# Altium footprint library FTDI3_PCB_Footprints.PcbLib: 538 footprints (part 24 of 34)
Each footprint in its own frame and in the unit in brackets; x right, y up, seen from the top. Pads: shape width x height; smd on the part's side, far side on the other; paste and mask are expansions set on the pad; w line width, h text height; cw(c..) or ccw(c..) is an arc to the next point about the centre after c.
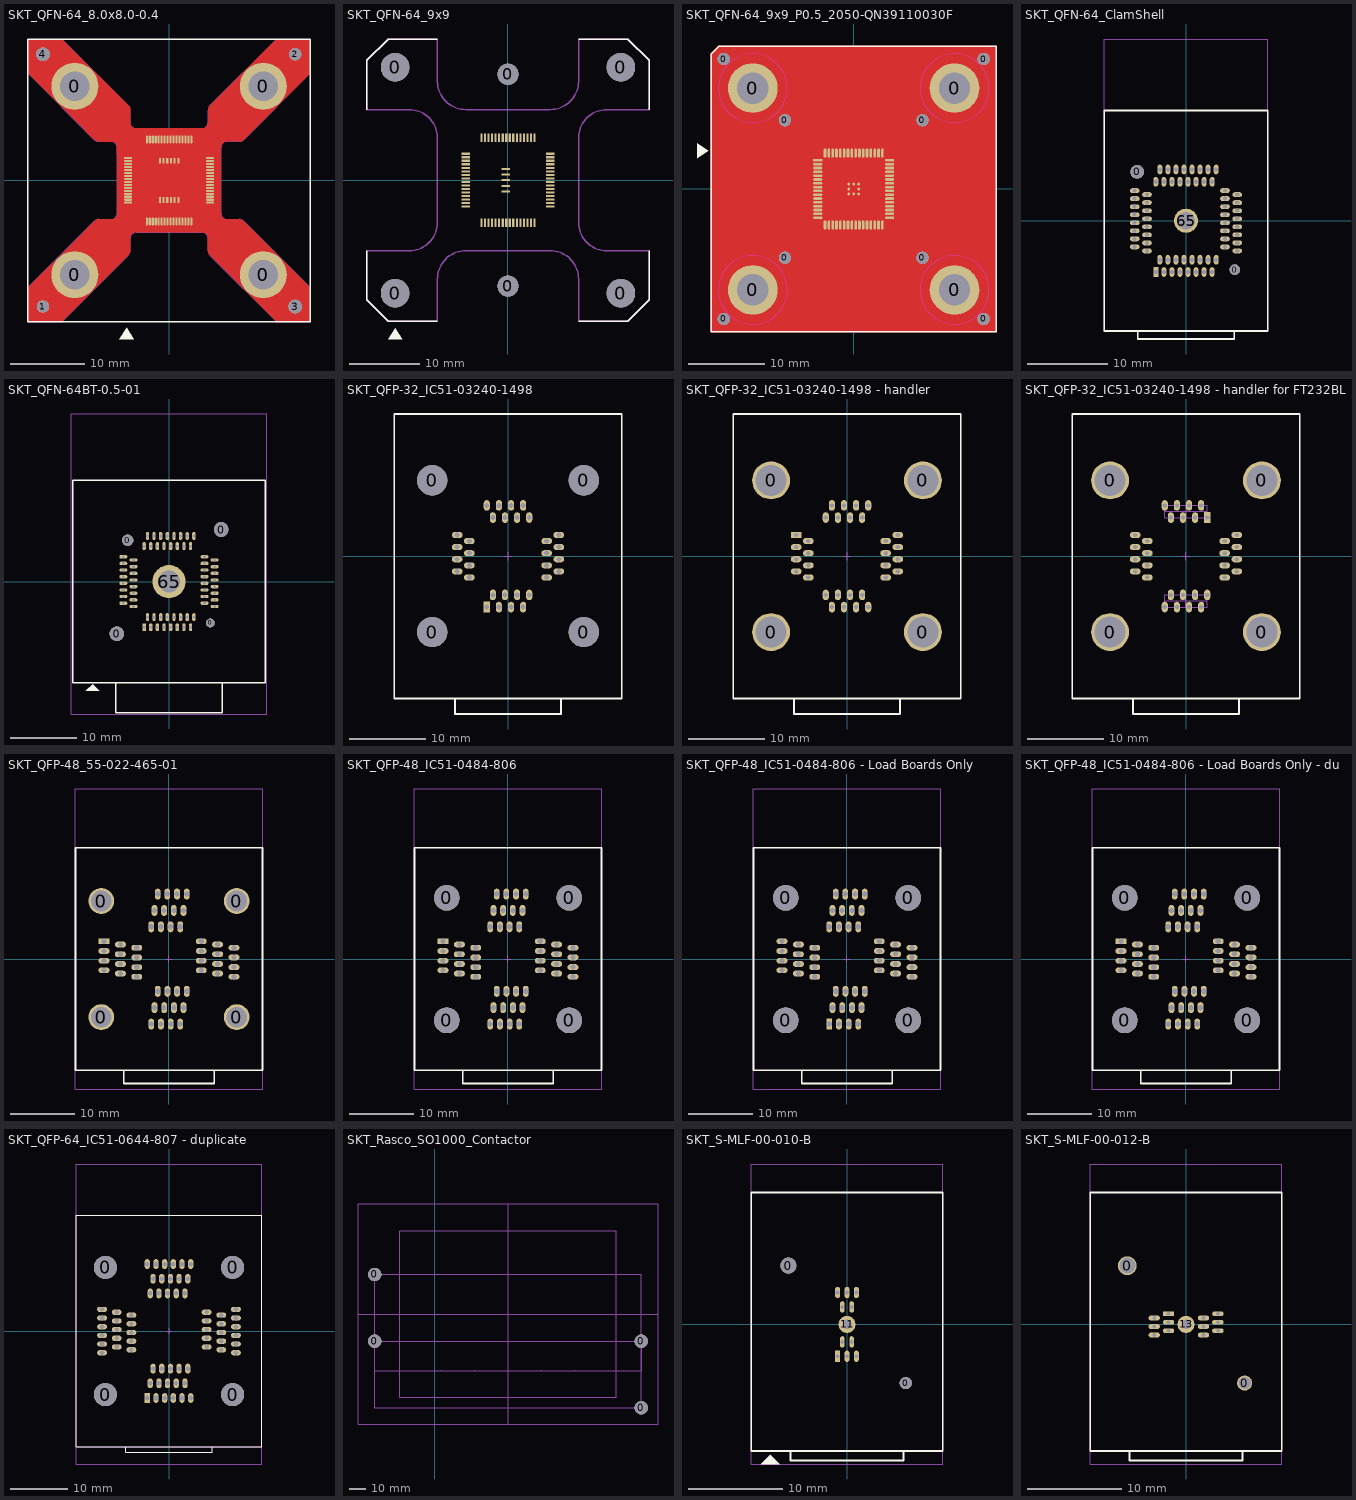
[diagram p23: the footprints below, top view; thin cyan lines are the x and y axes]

## SKT_QFN-64_8.0x8.0-0.4 [mm] "Load Board Socket for QFN-64; 8.0 x 8.0mm; 0.4mm pitch; Johnstech; Pad ROL(tm)200 series Production Test Contactor"
height 5.5
pads (84):
  round 6.35 hole 4: 0(-12.7,-12.7) 0(-12.7,12.7) 0(12.7,-12.7) 0(12.7,12.7)
  round 1.65 hole 1.65 unplated: 1(-17,-17) 2(17,17)
  oval 0.279x1.07 smd: 1(-3,-5.525) 2(-2.6,-5.525) 3(-2.2,-5.525) 4(-1.8,-5.525) 5(-1.4,-5.525) 6(-1,-5.525) 7(-0.6,-5.525) 8(-0.2,-5.525) 9(0.2,-5.525) 10(0.6,-5.525) 11(1,-5.525) 12(1.4,-5.525) 13(1.8,-5.525) 14(2.2,-5.525) 15(2.6,-5.525) 16(3,-5.525) 33(3,5.525) 34(2.6,5.525) 35(2.2,5.525) 36(1.8,5.525) 37(1.4,5.525) 38(1,5.525) 39(0.6,5.525) 40(0.2,5.525) 41(-0.2,5.525) 42(-0.6,5.525) 43(-1,5.525) 44(-1.4,5.525) 45(-1.8,5.525) 46(-2.2,5.525) 47(-2.6,5.525) 48(-3,5.525)
  round 1.85 hole 1.85 unplated: 3(17,-17) 4(-17,17)
  oval 1.07x0.279 smd: 17(5.525,-3) 18(5.525,-2.6) 19(5.525,-2.2) 20(5.525,-1.8) 21(5.525,-1.4) 22(5.525,-1) 23(5.525,-0.6) 24(5.525,-0.2) 25(5.525,0.2) 26(5.525,0.6) 27(5.525,1) 28(5.525,1.4) 29(5.525,1.8) 30(5.525,2.2) 31(5.525,2.6) 32(5.525,3) 49(-5.525,3) 50(-5.525,2.6) 51(-5.525,2.2) 52(-5.525,1.8) 53(-5.525,1.4) 54(-5.525,1) 55(-5.525,0.6) 56(-5.525,0.2) 57(-5.525,-0.2) 58(-5.525,-0.6) 59(-5.525,-1) 60(-5.525,-1.4) 61(-5.525,-1.8) 62(-5.525,-2.2) 63(-5.525,-2.6) 64(-5.525,-3)
  rect 0.28x0.8 smd: 65(-1.25,-2.65) 65(-1.25,2.65) 65(-0.75,-2.65) 65(-0.75,2.65) 65(-0.25,-2.65) 65(-0.25,2.65) 65(0.25,-2.65) 65(0.25,2.65) 65(0.75,-2.65) 65(0.75,2.65) 65(1.25,-2.65) 65(1.25,2.65)
Top Layer:
  pour cut-out: -19.05,19.06 -14.465,19.06 -14.465,19.05 -5.25,9.835 -5.25,7.52 -4.735,7.005 4.725,7.005 4.93,7.21 4.995,7.21 4.995,7.22 5.14,7.365 5.14,7.47 5.23,7.56 5.23,7.755 5.255,7.78 5.255,9.59 5.28,9.615 5.28,9.75 5.37,9.84 5.37,9.945 5.49,10.065 5.49,10.07 14.465,19.045 19.05,19.045 19.05,14.475 10.015,5.44 9.98,5.44 9.89,5.35 9.84,5.35 9.77,5.28 9.645,5.28 9.615,5.25 7.61,5.25 7.54,5.18 7.43,5.18 7.35,5.1 7.305,5.1 7.185,4.98 7.185,4.95 7.09,4.855 7.09,4.78 7.02,4.71 7.02,4.56 6.995,4.535 6.995,-4.515 7.015,-4.535 7.015,-4.675 7.055,-4.715 7.055,-4.795 7.14,-4.88 7.14,-4.92 7.37,-5.15 7.49,-5.15 7.565,-5.225 7.755,-5.225 7.785,-5.255 9.615,-5.255 9.64,-5.28 9.76,-5.28 9.82,-5.34 9.895,-5.34 10.04,-5.485 10.055,-5.485 19.045,-14.475 19.045,-19.055 18.81,-19.055 18.805,-19.06 14.48,-19.06 14.48,-19.05 5.34,-9.91 5.34,-9.83 5.3,-9.79 5.3,-9.735 5.275,-9.71 5.275,-9.64 5.25,-9.615 5.25,-9.525 5.245,-9.52 5.245,-7.72 5.23,-7.705 5.23,-7.585 5.19,-7.545 5.19,-7.465 5.135,-7.41 5.135,-7.385 5.06,-7.31 5.06,-7.285 4.975,-7.2 4.975,-7.195 4.96,-7.195 4.89,-7.125 4.86,-7.125 4.79,-7.055 4.705,-7.055 4.66,-7.01 4.54,-7.01 4.525,-6.995 -4.455,-6.995 -4.47,-7.01 -4.695,-7.01 -4.75,-7.065 -4.815,-7.065 -4.9,-7.15 -4.925,-7.15 -5.035,-7.26 -5.055,-7.26 -5.055,-7.285 -5.15,-7.38 -5.15,-7.425 -5.205,-7.48 -5.205,-7.59 -5.235,-7.62 -5.235,-7.805 -5.255,-7.825 -5.255,-9.69 -5.315,-9.75 -5.315,-9.845 -5.415,-9.945 -5.415,-9.985 -14.47,-19.04 -19.05,-19.04 -19.05,-14.455 -12.27,-7.7 -9.945,-5.39 -9.685,-5.265 -7.685,-5.245 -7.21,-5.03 -6.99,-4.495 -6.995,-2.835 -7,-0.085 -6.995,2.555 -7.02,4.655 -7.215,5 -7.595,5.23 -8.42,5.245 -9.27,5.23 -9.675,5.265 -9.985,5.41 -12.465,7.89 -19.07,14.485
Top Overlay:
  region: -5.73,-19.87 -4.73,-21.37 -6.73,-21.37
  lines w0.2: -19.05,-19.05 -19.05,19.05 19.05,19.05 19.05,-19.05 -19.05,-19.05
Top Solder:
  pour cut-out: -19.05,-19.05 -14.479,-19.05 -9.871,-14.443 -7.52,-12.08 -6.165,-10.736 -5.484,-10.056 -5.28,-9.8 -5.24,-9.55 -5.25,-9.3 -5.25,-7.8 -5.21,-7.49 -5.02,-7.24 -4.77,-7.04 -4.45,-7 4.45,-7 4.81,-7.05 5.05,-7.2 5.21,-7.48 5.25,-7.8 5.25,-9.49 5.3,-9.81 5.484,-10.056 14.479,-19.05 19.05,-19.05 19.05,-14.479 10.056,-5.484 9.8,-5.3 9.49,-5.25 7.8,-5.25 7.51,-5.19 7.26,-5.03 7.06,-4.77 7,-4.45 7,4.45 7.06,4.77 7.24,5.04 7.49,5.2 7.8,5.25 8.795,5.27 9.34,5.25 9.58,5.25 9.82,5.3 10.056,5.486 10.864,6.294 12.09,7.56 14.38,9.85 19.05,14.48 19.05,19.05 14.479,19.05 5.25,9.821 5.25,7.8 5.16,7.49 5.01,7.24 4.74,7.07 4.45,7 -4.45,7 -4.76,7.06 -5.04,7.23 -5.18,7.47 -5.25,7.8 -5.25,9.49 -5.32,9.81 -5.484,10.056 -14.479,19.05 -19.05,19.05 -19.05,14.479 -9.821,5.25 -7.8,5.25 -7.48,5.18 -7.22,4.99 -7.06,4.74 -7,4.45 -7,-4.45 -7.08,-4.78 -7.25,-5.04 -7.51,-5.18 -7.8,-5.25 -9.49,-5.25 -9.78,-5.3 -10.056,-5.484 -19.05,-14.479
M13_Assembly_Info:
  lines w0.1: -19.05,-19.05 -19.05,-14.479 -10.056,-5.484 cw(c-9.49,-6.05) -9.49,-5.25 -7.8,-5.25 ccw(c-7.8,-4.45) -7,-4.45 -7,4.45 ccw(c-7.8,4.45) -7.8,5.25 -9.49,5.25 cw(c-9.49,6.05) -10.056,5.484 -19.05,14.479 -19.05,19.05 -14.479,19.05 -5.484,10.056 cw(c-6.05,9.49) -5.25,9.49 -5.25,7.8 ccw(c-4.45,7.8) -4.45,7 4.45,7 ccw(c4.45,7.8) 5.25,7.8 5.25,9.49 cw(c6.05,9.49) 5.484,10.056 14.479,19.05 19.05,19.05 19.05,14.48 10.056,5.486 10.056,5.484 cw(c9.49,6.05) 9.49,5.25 7.8,5.25 ccw(c7.8,4.45) 7,4.45 7,-4.45 ccw(c7.8,-4.45) 7.8,-5.25 9.49,-5.25 cw(c9.49,-6.05) 10.056,-5.484 19.05,-14.479 19.05,-19.05 14.479,-19.05 5.484,-10.056 cw(c6.05,-9.49) 5.25,-9.49 5.25,-7.8 ccw(c4.45,-7.8) 4.45,-7 -4.45,-7 ccw(c-4.45,-7.8) -5.25,-7.8 -5.25,-9.49 cw(c-6.05,-9.49) -5.484,-10.056 -14.479,-19.05 -19.05,-19.05 ; -4,-4 4,-4 4,4 -4,4 -4,-4
M15_Country_Yard:
  lines w0.1: -0.5,0 0.5,0 ; 0,-0.5 0,0.5

## SKT_QFN-64_9x9 [mm]
pads (75):
  round 4.05 hole 4.05 unplated: 0(-16,-16) 0(-16,16) 0(16,-16) 0(16,16)
  round 3 hole 3 unplated: 0(0,-15) 0(0,15)
  rect 0.3x1.2 smd: 1(-3.75,-6) 2(-3.25,-6) 3(-2.75,-6) 4(-2.25,-6) 5(-1.75,-6) 6(-1.25,-6) 7(-0.75,-6) 8(-0.25,-6) 9(0.25,-6) 10(0.75,-6) 11(1.25,-6) 12(1.75,-6) 13(2.25,-6) 14(2.75,-6) 15(3.25,-6) 16(3.75,-6) 33(3.75,6) 34(3.25,6) 35(2.75,6) 36(2.25,6) 37(1.75,6) 38(1.25,6) 39(0.75,6) 40(0.25,6) 41(-0.25,6) 42(-0.75,6) 43(-1.25,6) 44(-1.75,6) 45(-2.25,6) 46(-2.75,6) 47(-3.25,6) 48(-3.75,6)
  rect 1.2x0.3 smd: 17(6,-3.75) 18(6,-3.25) 19(6,-2.75) 20(6,-2.25) 21(6,-1.75) 22(6,-1.25) 23(6,-0.75) 24(6,-0.25) 25(6,0.25) 26(6,0.75) 27(6,1.25) 28(6,1.75) 29(6,2.25) 30(6,2.75) 31(6,3.25) 32(6,3.75) 49(-6,3.75) 50(-6,3.25) 51(-6,2.75) 52(-6,2.25) 53(-6,1.75) 54(-6,1.25) 55(-6,0.75) 56(-6,0.25) 57(-6,-0.25) 58(-6,-0.75) 59(-6,-1.25) 60(-6,-1.75) 61(-6,-2.25) 62(-6,-2.75) 63(-6,-3.25) 64(-6,-3.75) 65(-0.3,-1.6) 65(-0.3,-0.8) 65(-0.3,0) 65(-0.3,0.8) 65(-0.3,1.6)
Top Overlay:
  region: -16,-21 -15,-22.5 -17,-22.5
  lines w0.2: -20,-10 -20,-16.975 -16.975,-20 -10,-20 ; -20,10 -20,16.975 -16.975,20 -10,20 ; 10,-20 16.975,-20 20,-16.975 20,-10 ; 10,20 16.975,20 20,16.975 20,10
M13_Assembly_Info:
  lines w0.2: 13.975,-10 20,-10 20,-16.975 16.975,-20 10,-20 10,-14 ccw(c6,-14) 6,-10 -6,-10 ccw(c-6,-14) -10,-14 -10,-20 -16.975,-20 -20,-16.975 -20,-10 -14,-10 ccw(c-14,-6) -10,-6 -10,6 ccw(c-14,6) -14,10 -20,10 -20,16.975 -16.975,20 -10,20 -10,14 ccw(c-6,14) -6,10 6,10 ccw(c6,14) 10,14 10,20 16.975,20 20,16.975 20,10 13.975,10 ; 14,-10 cw(c14,-6) 10,-6 10,6 cw(c14,6) 14,10

## SKT_QFN-64_9x9_P0.5_2050-QN39110030F [mm] "Tai-Chen Precision Inc. QFN-64 9x9mm body; 0.5mm pitch; Test Socket; 2050-QN39110030F"
height 6.6
pads (84):
  round 1.6 hole 1.6 unplated: 0(-17,-17) 0(-17,17) 0(-9,-9) 0(-9,9) 0(9,-9) 0(9,9) 0(17,-17) 0(17,17)
  round 6.5 hole 4.1: 0(-13.2,-13.2) 0(-13.2,13.2) 0(13.2,-13.2) 0(13.2,13.2)
  rect 1.2x0.35 smd: 1(-4.7,3.75)
  oval 1.2x0.35 smd: 2(-4.7,3.25) 3(-4.7,2.75) 4(-4.7,2.25) 5(-4.7,1.75) 6(-4.7,1.25) 7(-4.7,0.75) 8(-4.7,0.25) 9(-4.7,-0.25) 10(-4.7,-0.75) 11(-4.7,-1.25) 12(-4.7,-1.75) 13(-4.7,-2.25) 14(-4.7,-2.75) 15(-4.7,-3.25) 16(-4.7,-3.75) 33(4.7,-3.75) 34(4.7,-3.25) 35(4.7,-2.75) 36(4.7,-2.25) 37(4.7,-1.75) 38(4.7,-1.25) 39(4.7,-0.75) 40(4.7,-0.25) 41(4.7,0.25) 42(4.7,0.75) 43(4.7,1.25) 44(4.7,1.75) 45(4.7,2.25) 46(4.7,2.75) 47(4.7,3.25) 48(4.7,3.75)
  oval 0.35x1.2 smd: 17(-3.75,-4.7) 18(-3.25,-4.7) 19(-2.75,-4.7) 20(-2.25,-4.7) 21(-1.75,-4.7) 22(-1.25,-4.7) 23(-0.75,-4.7) 24(-0.25,-4.7) 25(0.25,-4.7) 26(0.75,-4.7) 27(1.25,-4.7) 28(1.75,-4.7) 29(2.25,-4.7) 30(2.75,-4.7) 31(3.25,-4.7) 32(3.75,-4.7) 49(3.75,4.7) 50(3.25,4.7) 51(2.75,4.7) 52(2.25,4.7) 53(1.75,4.7) 54(1.25,4.7) 55(0.75,4.7) 56(0.25,4.7) 57(-0.25,4.7) 58(-0.75,4.7) 59(-1.25,4.7) 60(-1.75,4.7) 61(-2.25,4.7) 62(-2.75,4.7) 63(-3.25,4.7) 64(-3.75,4.7)
  round 0.35 smd: 65(-0.66,-0.65) 65(-0.66,0) 65(-0.66,0.65) 65(-0.01,-0.65) 65(-0.01,0.65) 65(0.64,-0.65) 65(0.64,0) 65(0.64,0.65)
Top Layer:
  pour cut-out: -18.75,-18.75 -18.75,17.725 -17.725,18.75 18.75,18.75 18.75,-18.75
Top Overlay:
  region: -19,5 -20.5,4 -20.5,6
  lines w0.2: -18.65,-18.65 18.65,-18.65 18.65,18.65 -17.65,18.65 -18.65,17.65 -18.65,-18.65
Keep-Out Layer:
  circle w0.1: c-13.2,-13.2 r4.5
  circle w0.1: c13.2,-13.2 r4.5
  circle w0.1: c13.2,13.2 r4.5
  circle w0.1: c-13.2,13.2 r4.5
M15_Country_Yard:
  lines w0.1: -0.5,0 0.5,0 ; 0,-0.5 0,0.5

## SKT_QFN-64_ClamShell [mm] "Test & Burn socket for QFN-64"
height 15
pads (67):
  round 1.7 hole 1.7: 0(-6.075,6.075)
  round 1.3 hole 1.3: 0(6.075,-6.072)
  rect 0.6x1.2 hole 0.5: 1(-3.75,-6.375)
  oval 0.6x1.2 hole 0.5: 2(-3.25,-4.85) 3(-2.75,-6.375) 4(-2.25,-4.85) 5(-1.75,-6.375) 6(-1.25,-4.85) 7(-0.75,-6.375) 8(-0.25,-4.85) 9(0.25,-6.375) 10(0.75,-4.85) 11(1.25,-6.375) 12(1.75,-4.85) 13(2.25,-6.375) 14(2.75,-4.85) 15(3.25,-6.375) 16(3.75,-4.85) 33(3.75,6.376) 34(3.25,4.851) 35(2.75,6.376) 36(2.25,4.851) 37(1.75,6.376) 38(1.25,4.851) 39(0.75,6.376) 40(0.25,4.851) 41(-0.25,6.376) 42(-0.75,4.851) 43(-1.25,6.376) 44(-1.75,4.851) 45(-2.25,6.376) 46(-2.75,4.851) 47(-3.25,6.376) 48(-3.75,4.851)
  oval 1.2x0.6 hole 0.5: 17(6.373,-3.75) 18(4.848,-3.25) 19(6.373,-2.75) 20(4.848,-2.25) 21(6.373,-1.75) 22(4.848,-1.25) 23(6.373,-0.75) 24(4.848,-0.25) 25(6.373,0.25) 26(4.848,0.75) 27(6.373,1.25) 28(4.848,1.75) 29(6.373,2.25) 30(4.848,2.75) 31(6.373,3.25) 32(4.848,3.75) 49(-6.376,3.75) 50(-4.851,3.25) 51(-6.376,2.75) 52(-4.851,2.25) 53(-6.376,1.75) 54(-4.851,1.25) 55(-6.376,0.75) 56(-4.851,0.25) 57(-6.376,-0.25) 58(-4.851,-0.75) 59(-6.376,-1.25) 60(-4.851,-1.75) 61(-6.376,-2.25) 62(-4.851,-2.75) 63(-6.376,-3.25) 64(-4.851,-3.75)
  round 3 hole 2.2: 65(0,0)
Top Overlay:
  lines w0.2: -6,-13.715 -6,-14.707 6,-14.707 6,-13.715 ; -10.16,-13.715 -10.16,13.715 10.16,13.715 10.16,-13.715 -10.16,-13.715
M13_Assembly_Info:
  lines w0.1: -10.16,-13.715 -10.16,13.715 10.16,13.715 10.16,-13.715 -10.16,-13.715
M15_Country_Yard:
  lines w0.1: -10.16,13.715 -10.16,22.604 10.16,22.604 10.16,13.715

## SKT_QFN-64BT-0.5-01 [mm] "QFN-64BT-0.5-01 clamshell socket for QFN50P900X900X90-64"
height 16.7
pads (69):
  round 2.2 hole 2.2: 0(-7.85,-7.85) 0(7.85,7.85)
  round 1.7 hole 1.7: 0(-6.225,6.225)
  round 1.32 hole 1.32 unplated: 0(6.225,-6.225)
  rect 0.5x1.2 hole 0.4: 1(-3.75,-6.875)
  oval 0.5x1.2 hole 0.4: 2(-3.25,-5.35) 3(-2.75,-6.875) 4(-2.25,-5.35) 5(-1.75,-6.875) 6(-1.25,-5.35) 7(-0.75,-6.875) 8(-0.25,-5.35) 9(0.25,-6.875) 10(0.75,-5.35) 11(1.25,-6.875) 12(1.75,-5.35) 13(2.25,-6.875) 14(2.75,-5.35) 15(3.25,-6.875) 16(3.75,-5.35) 33(3.75,6.875) 34(3.25,5.35) 35(2.75,6.875) 36(2.25,5.35) 37(1.75,6.875) 38(1.25,5.35) 39(0.75,6.875) 40(0.25,5.35) 41(-0.25,6.875) 42(-0.75,5.35) 43(-1.25,6.875) 44(-1.75,5.35) 45(-2.25,6.875) 46(-2.75,5.35) 47(-3.25,6.875) 48(-3.75,5.35)
  oval 1.2x0.5 hole 0.4: 17(6.875,-3.75) 18(5.35,-3.25) 19(6.875,-2.75) 20(5.35,-2.25) 21(6.875,-1.75) 22(5.35,-1.25) 23(6.875,-0.75) 24(5.35,-0.25) 25(6.875,0.25) 26(5.35,0.75) 27(6.875,1.25) 28(5.35,1.75) 29(6.875,2.25) 30(5.35,2.75) 31(6.875,3.25) 32(5.35,3.75) 49(-6.875,3.75) 50(-5.35,3.25) 51(-6.875,2.75) 52(-5.35,2.25) 53(-6.875,1.75) 54(-5.35,1.25) 55(-6.875,0.75) 56(-5.35,0.25) 57(-6.875,-0.25) 58(-5.35,-0.75) 59(-6.875,-1.25) 60(-5.35,-1.75) 61(-6.875,-2.25) 62(-5.35,-2.75) 63(-6.875,-3.25) 64(-5.35,-3.75)
  round 5 hole 3.3: 65(0,0)
Top Overlay:
  region: -11.51,-15.45 -12.51,-16.45 -10.51,-16.45
  lines w0.2: -8,-15.25 -8,-19.75 8,-19.75 8,-15.25 ; -14.5,-15.25 14.5,-15.25 14.5,15.25 -14.5,15.25 -14.5,-15.25
M15_Country_Yard:
  lines w0.1: -14.69,-19.94 -14.69,25.25 14.69,25.25 14.69,-19.94 -14.69,-19.94

## SKT_QFP-32_IC51-03240-1498 [mm] "Test & Burn socket for QFP-32, 0.8mm pitch, 7x7mm body. Yamaichi IC51-03240-1498"
height 18.6
pads (36):
  round 4 hole 4 unplated: 0(-10,-10) 0(-10,10) 0(10,-10) 0(10,10)
  rect 0.8x1.4 hole 0.65: 1(-2.8,-6.7)
  oval 0.8x1.4 hole 0.65: 2(-2,-5.1) 3(-1.2,-6.7) 4(-0.4,-5.1) 5(0.4,-6.7) 6(1.2,-5.1) 7(2,-6.7) 8(2.8,-5.1) 17(2.8,5.1) 18(2,6.7) 19(1.2,5.1) 20(0.4,6.7) 21(-0.4,5.1) 22(-1.2,6.7) 23(-2,5.1) 24(-2.8,6.7)
  oval 1.4x0.8 hole 0.65: 9(5.1,-2.8) 10(6.7,-2) 11(5.1,-1.2) 12(6.7,-0.4) 13(5.1,0.4) 14(6.7,1.2) 15(5.1,2) 16(6.7,2.8) 25(-6.7,2.8) 26(-5.1,2) 27(-6.7,1.2) 28(-5.1,0.4) 29(-6.7,-0.4) 30(-5.1,-1.2) 31(-6.7,-2) 32(-5.1,-2.8)
Top Overlay:
  lines w0.25: -7,-20.8 -7,-18.75 7,-18.75 7,-20.8 -7,-20.8
  lines w0.254: -15,-18.75 -15,18.75 15,18.75 15,-18.75 -15,-18.75
M15_Country_Yard:
  lines w0.1: -0.5,0 0.5,0 ; 0,-0.5 0,0.5

## SKT_QFP-32_IC51-03240-1498 - handler [mm] "Test & Burn socket for QFP-32, 0.8mm pitch, 7x7mm body. Yamaichi IC51-03240-1498"
height 18.6
pads (36):
  round 5 hole 4.1: 0(-10,-10) 0(-10,10) 0(10,-10) 0(10,10)
  rect 1.4x0.8 hole 0.55: 1(-6.7,2.8)
  oval 1.4x0.8 hole 0.55: 2(-5.1,2) 3(-6.7,1.2) 4(-5.1,0.4) 5(-6.7,-0.4) 6(-5.1,-1.2) 7(-6.7,-2) 8(-5.1,-2.8) 17(5.1,-2.8) 18(6.7,-2) 19(5.1,-1.2) 20(6.7,-0.4) 21(5.1,0.4) 22(6.7,1.2) 23(5.1,2) 24(6.7,2.8)
  oval 0.8x1.4 hole 0.55: 9(-2.8,-5.1) 10(-2,-6.7) 11(-1.2,-5.1) 12(-0.4,-6.7) 13(0.4,-5.1) 14(1.2,-6.7) 15(2,-5.1) 16(2.8,-6.7) 25(2.8,6.7) 26(2,5.1) 27(1.2,6.7) 28(0.4,5.1) 29(-0.4,6.7) 30(-1.2,5.1) 31(-2,6.7) 32(-2.8,5.1)
Top Overlay:
  lines w0.25: -7,-20.8 -7,-18.75 7,-18.75 7,-20.8 -7,-20.8
  lines w0.254: -15,-18.75 -15,18.75 15,18.75 15,-18.75 -15,-18.75
M15_Country_Yard:
  lines w0.1: -0.5,0 0.5,0 ; 0,-0.5 0,0.5

## SKT_QFP-32_IC51-03240-1498 - handler for FT232BL [mm] "Test & Burn socket for QFP-32, 0.8mm pitch, 7x7mm body. Yamaichi IC51-03240-1498"
height 18.6
pads (36):
  round 5 hole 4.1: 0(-10,-10) 0(-10,10) 0(10,-10) 0(10,10)
  rect 0.8x1.4 hole 0.55: 1(2.8,5.1)
  oval 0.8x1.4 hole 0.55: 2(2,6.7) 3(1.2,5.1) 4(0.4,6.7) 5(-0.4,5.1) 6(-1.2,6.7) 7(-2,5.1) 8(-2.8,6.7) 17(-2.8,-6.7) 18(-2,-5.1) 19(-1.2,-6.7) 20(-0.4,-5.1) 21(0.4,-6.7) 22(1.2,-5.1) 23(2,-6.7) 24(2.8,-5.1)
  oval 1.4x0.8 hole 0.55: 9(-6.7,2.8) 10(-5.1,2) 11(-6.7,1.2) 12(-5.1,0.4) 13(-6.7,-0.4) 14(-5.1,-1.2) 15(-6.7,-2) 16(-5.1,-2.8) 25(5.1,-2.8) 26(6.7,-2) 27(5.1,-1.2) 28(6.7,-0.4) 29(5.1,0.4) 30(6.7,1.2) 31(5.1,2) 32(6.7,2.8)
Top Overlay:
  lines w0.25: -7,-20.8 7,-20.8 7,-18.75 -7,-18.75 -7,-20.8
  lines w0.254: -15,-18.75 15,-18.75 15,18.75 -15,18.75 -15,-18.75
M15_Country_Yard:
  lines w0.1: -2.8,-5.9 2.8,-5.9 ; -2.8,5.9 2.8,5.9 ; -0.5,0 0.5,0 ; 0,-6.7 0,-5.1 ; 0,-0.5 0,0.5 ; 0,5.1 0,6.7 ; -2.8,-6.7 2.8,-6.7 2.8,-5.1 -2.8,-5.1 -2.8,-6.7 ; -2.8,5.1 -2.8,6.7 2.8,6.7 2.8,5.1 -2.8,5.1

## SKT_QFP-48_55-022-465-01 [mm] "Test & Burn socket for QFP-48, 0.5mm pitch, 7x7mm body. Enplas, 55-022-465-01"
height 18.6
pads (52):
  round 4 hole 3.2 unplated: 0(-10.5,-9) 0(-10.5,9) 0(10.5,-9) 0(10.5,9)
  rect 1.7x0.9 hole 0.8: 1(-10.08,2.75)
  oval 1.7x0.9 hole 0.8: 2(-7.54,2.25) 3(-5,1.75) 4(-10.08,1.25) 5(-7.54,0.75) 6(-5,0.25) 7(-10.08,-0.26) 8(-7.54,-0.76) 9(-5,-1.26) 10(-10.08,-1.75) 11(-7.54,-2.25) 12(-5,-2.75) 25(10.08,-2.75) 26(7.54,-2.25) 27(5,-1.75) 28(10.08,-1.25) 29(7.54,-0.75) 30(5,-0.25) 31(10.08,0.26) 32(7.54,0.76) 33(5,1.26) 34(10.08,1.75) 35(7.54,2.25) 36(5,2.75)
  oval 0.9x1.7 hole 0.8: 13(-2.75,-10.08) 14(-2.25,-7.54) 15(-1.75,-5) 16(-1.25,-10.08) 17(-0.75,-7.54) 18(-0.25,-5) 19(0.26,-10.08) 20(0.76,-7.54) 21(1.26,-5) 22(1.75,-10.08) 23(2.25,-7.54) 24(2.75,-5) 37(2.75,10.08) 38(2.25,7.54) 39(1.75,5) 40(1.25,10.08) 41(0.75,7.54) 42(0.25,5) 43(-0.26,10.08) 44(-0.76,7.54) 45(-1.26,5) 46(-1.75,10.08) 47(-2.25,7.54) 48(-2.75,5)
Top Overlay:
  lines w0.25: -7,-17.25 -7,-19.3 7,-19.3 7,-17.25 ; -14.5,-17.25 -14.5,17.25 14.5,17.25 14.5,-17.25 -14.5,-17.25
M15_Country_Yard:
  lines w0.1: -0.5,0 0.5,0 ; 0,-0.5 0,0.5 ; -14.5,-20.15 14.5,-20.15 14.5,26.37 -14.5,26.37 -14.5,-20.15
3D body: height 15, standoff 0, extent -14.5,-17.25 14.5,17.25

## SKT_QFP-48_IC51-0484-806 [mm] "Test & Burn socket for QFP-48, 0.5mm pitch, 7x7mm body. Yamaichi, IC51-0484-806"
height 18.6
pads (52):
  round 4 hole 4 unplated: 0(-9.5,-9.5) 0(-9.5,9.5) 0(9.5,-9.5) 0(9.5,9.5)
  rect 1.7x0.9 hole 0.8: 1(-10.08,2.75)
  oval 1.7x0.9 hole 0.8: 2(-7.54,2.25) 3(-5,1.75) 4(-10.08,1.25) 5(-7.54,0.75) 6(-5,0.25) 7(-10.08,-0.26) 8(-7.54,-0.76) 9(-5,-1.26) 10(-10.08,-1.75) 11(-7.54,-2.25) 12(-5,-2.75) 25(10.08,-2.75) 26(7.54,-2.25) 27(5,-1.75) 28(10.08,-1.25) 29(7.54,-0.75) 30(5,-0.25) 31(10.08,0.26) 32(7.54,0.76) 33(5,1.26) 34(10.08,1.75) 35(7.54,2.25) 36(5,2.75)
  oval 0.9x1.7 hole 0.8: 13(-2.75,-10.08) 14(-2.25,-7.54) 15(-1.75,-5) 16(-1.25,-10.08) 17(-0.75,-7.54) 18(-0.25,-5) 19(0.26,-10.08) 20(0.76,-7.54) 21(1.26,-5) 22(1.75,-10.08) 23(2.25,-7.54) 24(2.75,-5) 37(2.75,10.08) 38(2.25,7.54) 39(1.75,5) 40(1.25,10.08) 41(0.75,7.54) 42(0.25,5) 43(-0.26,10.08) 44(-0.76,7.54) 45(-1.26,5) 46(-1.75,10.08) 47(-2.25,7.54) 48(-2.75,5)
Top Overlay:
  lines w0.25: -7,-17.25 -7,-19.3 7,-19.3 7,-17.25 ; -14.5,-17.25 14.5,-17.25 14.5,17.25 -14.5,17.25 -14.5,-17.25
M15_Country_Yard:
  lines w0.1: -0.5,0 0.5,0 ; 0,-0.5 0,0.5 ; -14.5,-20.15 -14.5,26.37 14.5,26.37 14.5,-20.15 -14.5,-20.15
3D body: height 15, standoff 0, extent -14.5,-17.25 14.5,17.25

## SKT_QFP-48_IC51-0484-806 - Load Boards Only [mm] "Test & Burn socket for QFP-48, 0.5mm pitch, 7x7mm body. Yamaichi, IC51-0484-806; Use only for Load Boards; Pin No. 1 rotated by 90 degrees"
height 18.6
pads (52):
  round 4 hole 4 unplated: 0(-9.5,-9.5) 0(-9.5,9.5) 0(9.5,-9.5) 0(9.5,9.5)
  rect 0.9x1.7 hole 0.8: 1(-2.75,-10.08)
  oval 0.9x1.7 hole 0.8: 2(-2.25,-7.54) 3(-1.75,-5) 4(-1.25,-10.08) 5(-0.75,-7.54) 6(-0.25,-5) 7(0.26,-10.08) 8(0.76,-7.54) 9(1.26,-5) 10(1.75,-10.08) 11(2.25,-7.54) 12(2.75,-5) 25(2.75,10.08) 26(2.25,7.54) 27(1.75,5) 28(1.25,10.08) 29(0.75,7.54) 30(0.25,5) 31(-0.26,10.08) 32(-0.76,7.54) 33(-1.26,5) 34(-1.75,10.08) 35(-2.25,7.54) 36(-2.75,5)
  oval 1.7x0.9 hole 0.8: 13(10.08,-2.75) 14(7.54,-2.25) 15(5,-1.75) 16(10.08,-1.25) 17(7.54,-0.75) 18(5,-0.25) 19(10.08,0.26) 20(7.54,0.76) 21(5,1.26) 22(10.08,1.75) 23(7.54,2.25) 24(5,2.75) 37(-10.08,2.75) 38(-7.54,2.25) 39(-5,1.75) 40(-10.08,1.25) 41(-7.54,0.75) 42(-5,0.25) 43(-10.08,-0.26) 44(-7.54,-0.76) 45(-5,-1.26) 46(-10.08,-1.75) 47(-7.54,-2.25) 48(-5,-2.75)
Top Overlay:
  lines w0.25: -7,-17.25 -7,-19.3 7,-19.3 7,-17.25 ; -14.5,-17.25 14.5,-17.25 14.5,17.25 -14.5,17.25 -14.5,-17.25
M15_Country_Yard:
  lines w0.1: -0.5,0 0.5,0 ; 0,-0.5 0,0.5 ; -14.5,-20.15 -14.5,26.37 14.5,26.37 14.5,-20.15 -14.5,-20.15
3D body: height 15, standoff 0, extent -14.5,-17.25 14.5,17.25

## SKT_QFP-48_IC51-0484-806 - Load Boards Only - duplicate1 [mm] "Test & Burn socket for QFP-48, 0.5mm pitch, 7x7mm body. Yamaichi, IC51-0484-806; Use only for Load Boards; Pin No. 1 rotated by 180 degrees"
height 18.6
pads (52):
  round 4 hole 4 unplated: 0(-9.5,-9.5) 0(-9.5,9.5) 0(9.5,-9.5) 0(9.5,9.5)
  rect 1.7x0.9 hole 0.8: 1(-10.08,2.75)
  oval 1.7x0.9 hole 0.8: 2(-7.54,2.25) 3(-5,1.75) 4(-10.08,1.25) 5(-7.54,0.75) 6(-5,0.25) 7(-10.08,-0.26) 8(-7.54,-0.76) 9(-5,-1.26) 10(-10.08,-1.75) 11(-7.54,-2.25) 12(-5,-2.75) 25(10.08,-2.75) 26(7.54,-2.25) 27(5,-1.75) 28(10.08,-1.25) 29(7.54,-0.75) 30(5,-0.25) 31(10.08,0.26) 32(7.54,0.76) 33(5,1.26) 34(10.08,1.75) 35(7.54,2.25) 36(5,2.75)
  oval 0.9x1.7 hole 0.8: 13(-2.75,-10.08) 14(-2.25,-7.54) 15(-1.75,-5) 16(-1.25,-10.08) 17(-0.75,-7.54) 18(-0.25,-5) 19(0.26,-10.08) 20(0.76,-7.54) 21(1.26,-5) 22(1.75,-10.08) 23(2.25,-7.54) 24(2.75,-5) 37(2.75,10.08) 38(2.25,7.54) 39(1.75,5) 40(1.25,10.08) 41(0.75,7.54) 42(0.25,5) 43(-0.26,10.08) 44(-0.76,7.54) 45(-1.26,5) 46(-1.75,10.08) 47(-2.25,7.54) 48(-2.75,5)
Top Overlay:
  lines w0.25: -7,-17.25 -7,-19.3 7,-19.3 7,-17.25 ; -14.5,-17.25 14.5,-17.25 14.5,17.25 -14.5,17.25 -14.5,-17.25
M15_Country_Yard:
  lines w0.1: -0.5,0 0.5,0 ; 0,-0.5 0,0.5 ; -14.5,-20.15 -14.5,26.37 14.5,26.37 14.5,-20.15 -14.5,-20.15
3D body: height 15, standoff 0, extent -14.5,-17.25 14.5,17.25

## SKT_QFP-64_IC51-0644-807 - duplicate [mm] "Test & Burn socket for QFP-64, 0.5mm pitch, 10x10mm body. Yamaichi, IC51-0644-807"
height 15
pads (68):
  round 4 hole 4 unplated: 0(-10.999,-10.997) 0(-10.999,10.999) 0(10.998,-10.997) 0(10.998,10.999)
  rect 0.9x1.7 hole 0.8: 1(-3.751,-11.582)
  oval 0.9x1.7 hole 0.8: 2(-3.251,-9.042) 3(-2.751,-6.502) 4(-2.251,-11.582) 5(-1.751,-9.042) 6(-1.251,-6.502) 7(-0.751,-11.582) 8(-0.251,-9.042) 9(0.249,-6.502) 10(0.749,-11.582) 11(1.249,-9.042) 12(1.749,-6.502) 13(2.249,-11.582) 14(2.749,-9.042) 15(3.249,-6.502) 16(3.749,-11.582) 33(3.749,11.582) 34(3.249,9.042) 35(2.749,6.502) 36(2.249,11.582) 37(1.749,9.042) 38(1.249,6.502) 39(0.749,11.582) 40(0.249,9.042) 41(-0.251,6.502) 42(-0.751,11.582) 43(-1.251,9.042) 44(-1.751,6.502) 45(-2.251,11.582) 46(-2.751,9.042) 47(-3.251,6.502) 48(-3.751,11.582)
  oval 1.7x0.9 hole 0.8: 17(11.582,-3.751) 18(9.042,-3.251) 19(6.502,-2.751) 20(11.582,-2.251) 21(9.042,-1.751) 22(6.502,-1.251) 23(11.582,-0.751) 24(9.042,-0.251) 25(6.502,0.249) 26(11.582,0.749) 27(9.042,1.249) 28(6.502,1.749) 29(11.582,2.249) 30(9.042,2.749) 31(6.502,3.249) 32(11.582,3.749) 49(-11.583,3.749) 50(-9.043,3.249) 51(-6.503,2.749) 52(-11.583,2.249) 53(-9.043,1.749) 54(-6.503,1.249) 55(-11.583,0.749) 56(-9.043,0.249) 57(-6.503,-0.251) 58(-11.583,-0.751) 59(-9.043,-1.251) 60(-6.503,-1.751) 61(-11.583,-2.251) 62(-9.043,-2.751) 63(-6.503,-3.251) 64(-11.583,-3.751)
Top Overlay:
  lines w0.2: -7.501,-19.999 -7.501,-20.93 7.499,-20.93 7.499,-19.999 ; -16,-19.999 16,-19.999 16,20.001 -16,20.001 -16,-19.999
M13_Assembly_Info:
  lines w0.1: -16,-19.999 16,-19.999 16,20.001 -16,20.001 -16,-19.999
M15_Country_Yard:
  lines w0.1: -16,-20 -16,-23 16,-23 16,-20 ; -16,20.001 -16,28.891 16,28.891 16,20.001 ; -0.5,0 0.5,0 ; 0,-0.5 0,0.5

## SKT_Rasco_SO1000_Contactor [mm]
pads (4):
  round 8 hole 8 unplated: 0(-35.93,134.21) 0(-35.93,174.21) 0(124.07,94.21) 0(124.07,134.21)
M15_Country_Yard:
  lines w0.1: -45.93,150.51 134.07,150.51 ; -35.93,116.43 124.07,116.43 ; -35.93,134.21 124.07,134.21 ; -20.93,150.51 109.07,150.51 ; 3.91,116.1 3.91,116.74 ; 24.23,116.1 24.23,116.74 ; 44.07,84.26 44.07,216.76 ; 44.07,94.21 44.07,174.21 ; 44.07,100.51 44.07,200.51 ; 63.91,116.1 63.91,116.74 ; 84.23,116.1 84.23,116.74 ; 124.3,116.43 124.3,134.21 ; -45.93,84.26 -45.93,216.76 134.07,216.76 134.07,84.26 -45.93,84.26 ; -35.93,94.21 -35.93,174.21 124.07,174.21 124.07,94.21 -35.93,94.21 ; -20.93,100.51 -20.93,200.51 109.07,200.51 109.07,100.51 -20.93,100.51

## SKT_S-MLF-00-010-B [mm] "Test & Burn socket for QFN-10, 0.5mm pitch, 3x3mm body. Emulation Technology S-MLF-00-010-B"
height 15
pads (13):
  round 1.7 hole 1.7 unplated: 0(-6.225,6.225)
  round 1.3 hole 1.3 unplated: 0(6.225,-6.225)
  rect 0.5x1.2 hole 0.4: 1(-1,-3.38)
  oval 0.5x1.2 hole 0.4: 2(-0.5,-1.855) 3(0,-3.38) 4(0.5,-1.855) 5(1,-3.38) 6(1,3.38) 7(0.5,1.855) 8(0,3.38) 9(-0.5,1.855) 10(-1,3.38)
  round 1.8 hole 1: 11(0,0)
Top Overlay:
  region: -8.14,-13.805 -7.14,-14.805 -9.14,-14.805
  lines w0.2: -6,-13.43 -6,-14.422 6,-14.422 6,-13.43 ; -10.16,-13.43 -10.16,14 10.16,14 10.16,-13.43 -10.16,-13.43
M15_Country_Yard:
  lines w0.1: -10.16,13.715 -10.16,17.01 10.16,17.01 10.16,13.715 ; -0.5,0 0.5,0 ; 0,-0.5 0,0.5 ; -10.16,-14.805 -10.16,14 10.16,14 10.16,-14.805 -10.16,-14.805

## SKT_S-MLF-00-012-B [mm] "Test & Burn socket for DFN-12, 0.45mm pitch, 3x3mm body. Emulation Technology S-MLF-00-012-B"
height 15
pads (15):
  round 2 hole 1.7: 0(-6.225,6.225)
  round 1.6 hole 1.3: 0(6.225,-6.225)
  rect 1.2x0.5 hole 0.4: 1(-1.85,1.125)
  oval 1.2x0.5 hole 0.4: 2(-3.375,0.675) 3(-1.85,0.225) 4(-3.375,-0.225) 5(-1.85,-0.675) 6(-3.375,-1.125) 7(1.855,-1.125) 8(3.38,-0.675) 9(1.855,-0.225) 10(3.38,0.225) 11(1.855,0.675) 12(3.38,1.125)
  round 1.8 hole 1: 13(0,0)
Top Overlay:
  lines w0.2: -6,-13.43 -6,-14.422 6,-14.422 6,-13.43 ; -10.16,-13.43 -10.16,14 10.16,14 10.16,-13.43 -10.16,-13.43
M15_Country_Yard:
  lines w0.1: -10.16,13.715 -10.16,17.01 10.16,17.01 10.16,13.715 ; -0.5,0 0.5,0 ; 0,-0.5 0,0.5 ; -10.16,-14.805 -10.16,14 10.16,14 10.16,-14.805 -10.16,-14.805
